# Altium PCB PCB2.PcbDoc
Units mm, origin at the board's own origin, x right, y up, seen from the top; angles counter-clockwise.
Board outline 94.87 x 64.13 mm, 2 copper layers (Top Layer, Bottom Layer); 28 components, 23 nets, 114 pads, 15 vias.
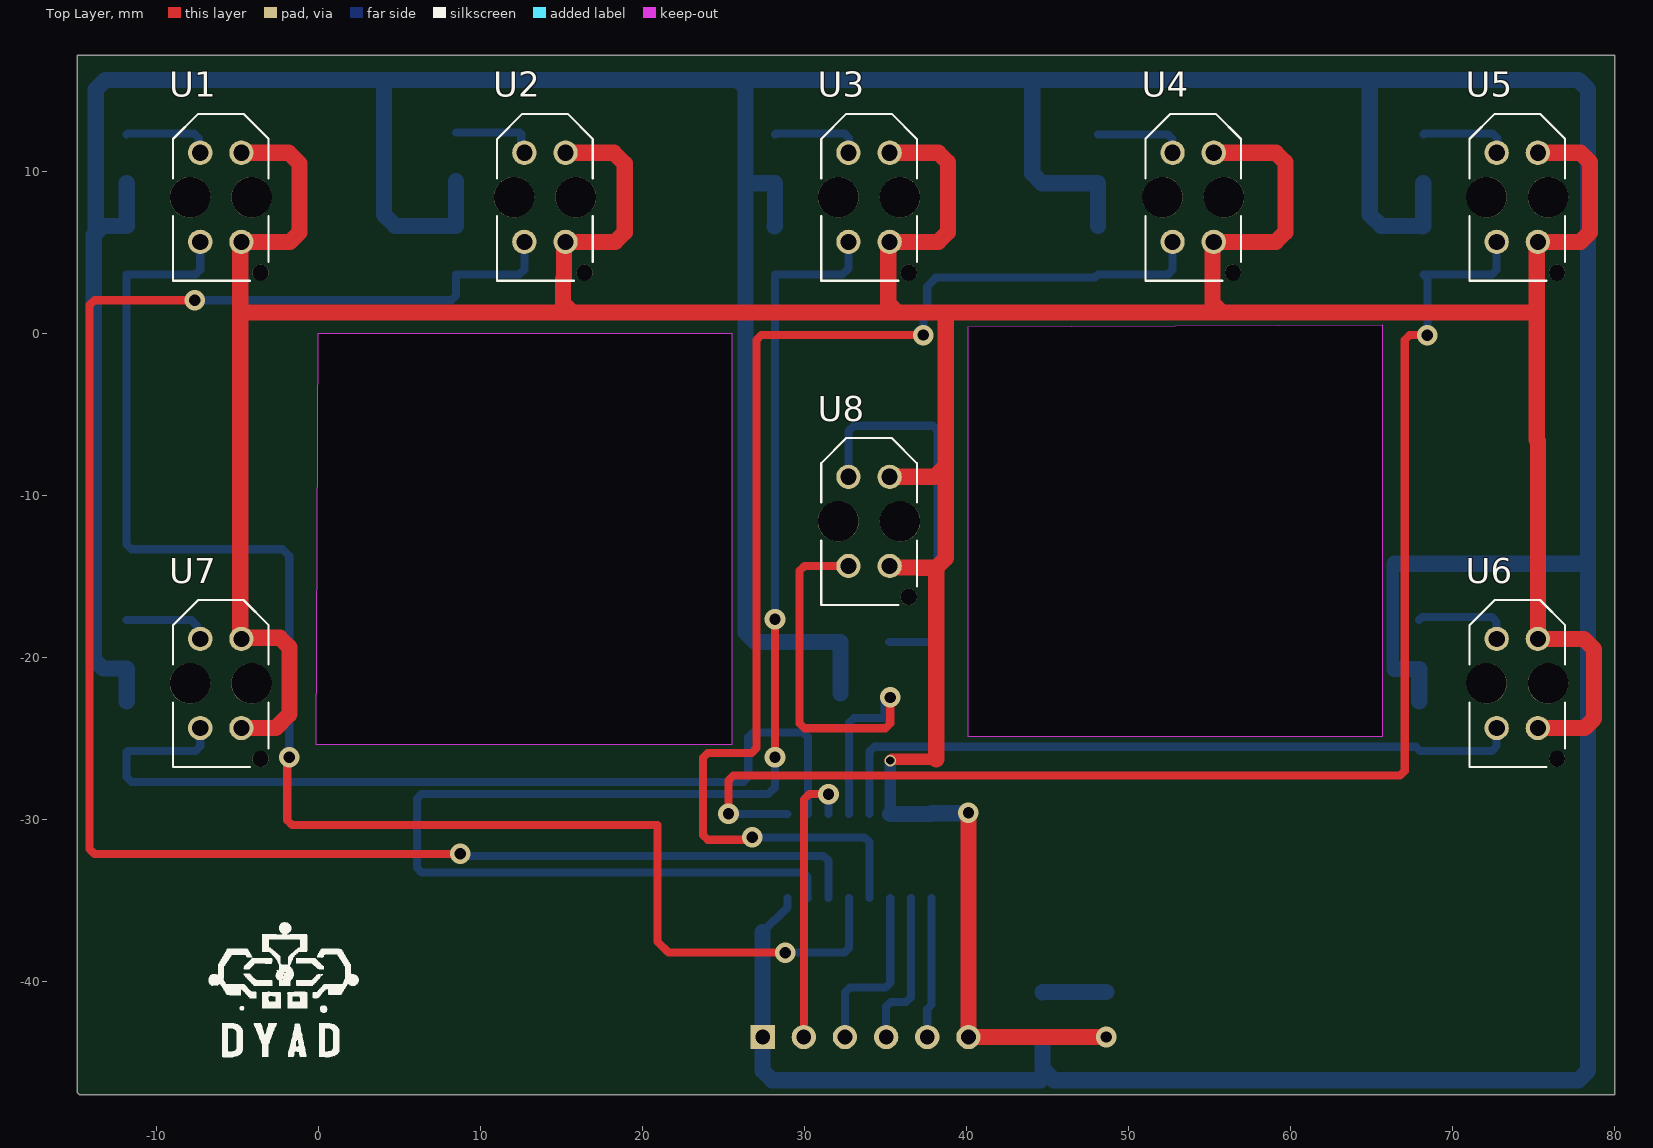
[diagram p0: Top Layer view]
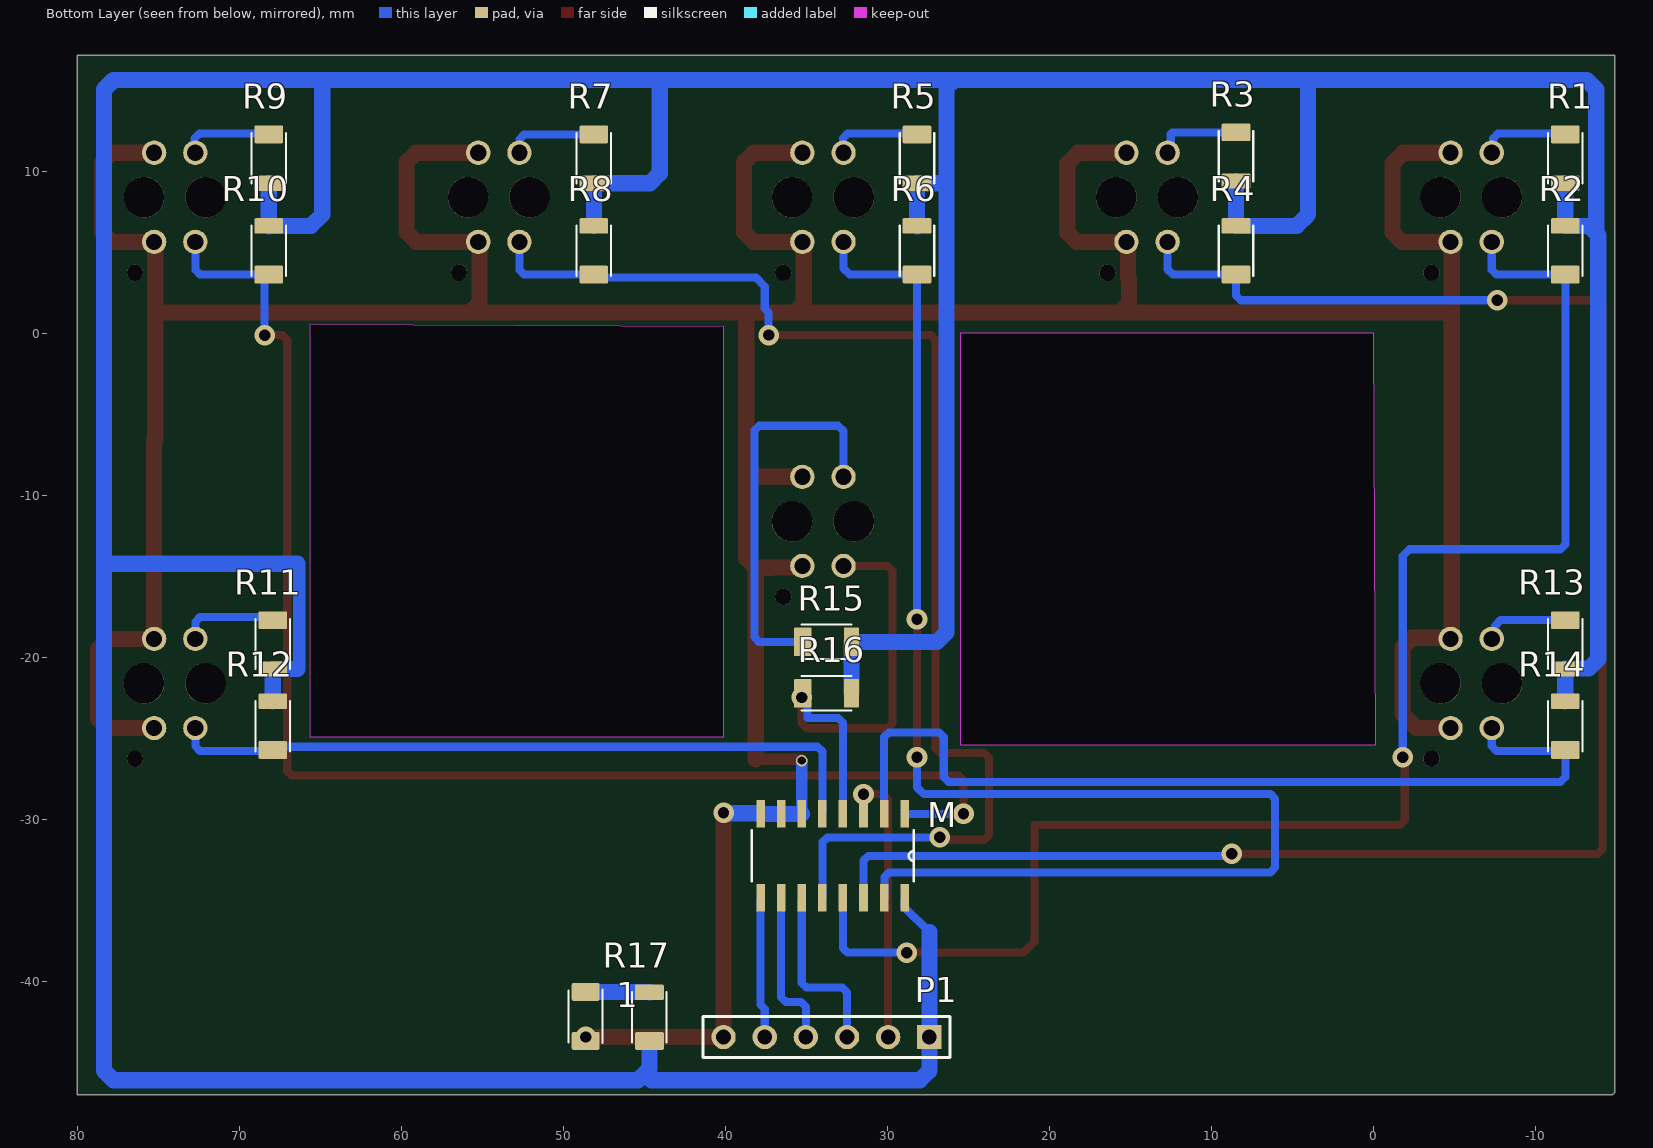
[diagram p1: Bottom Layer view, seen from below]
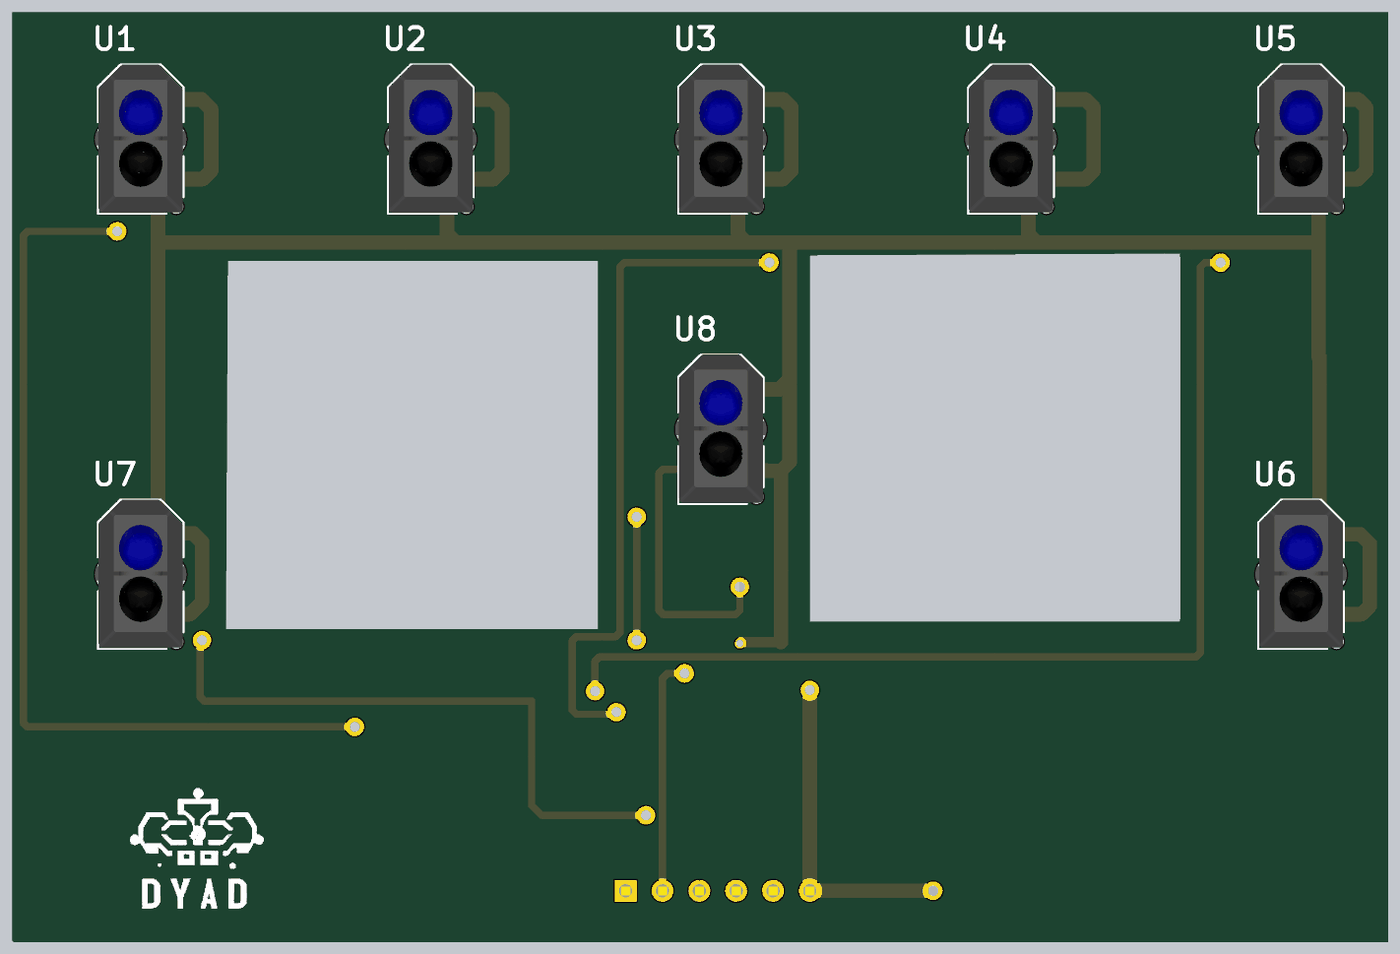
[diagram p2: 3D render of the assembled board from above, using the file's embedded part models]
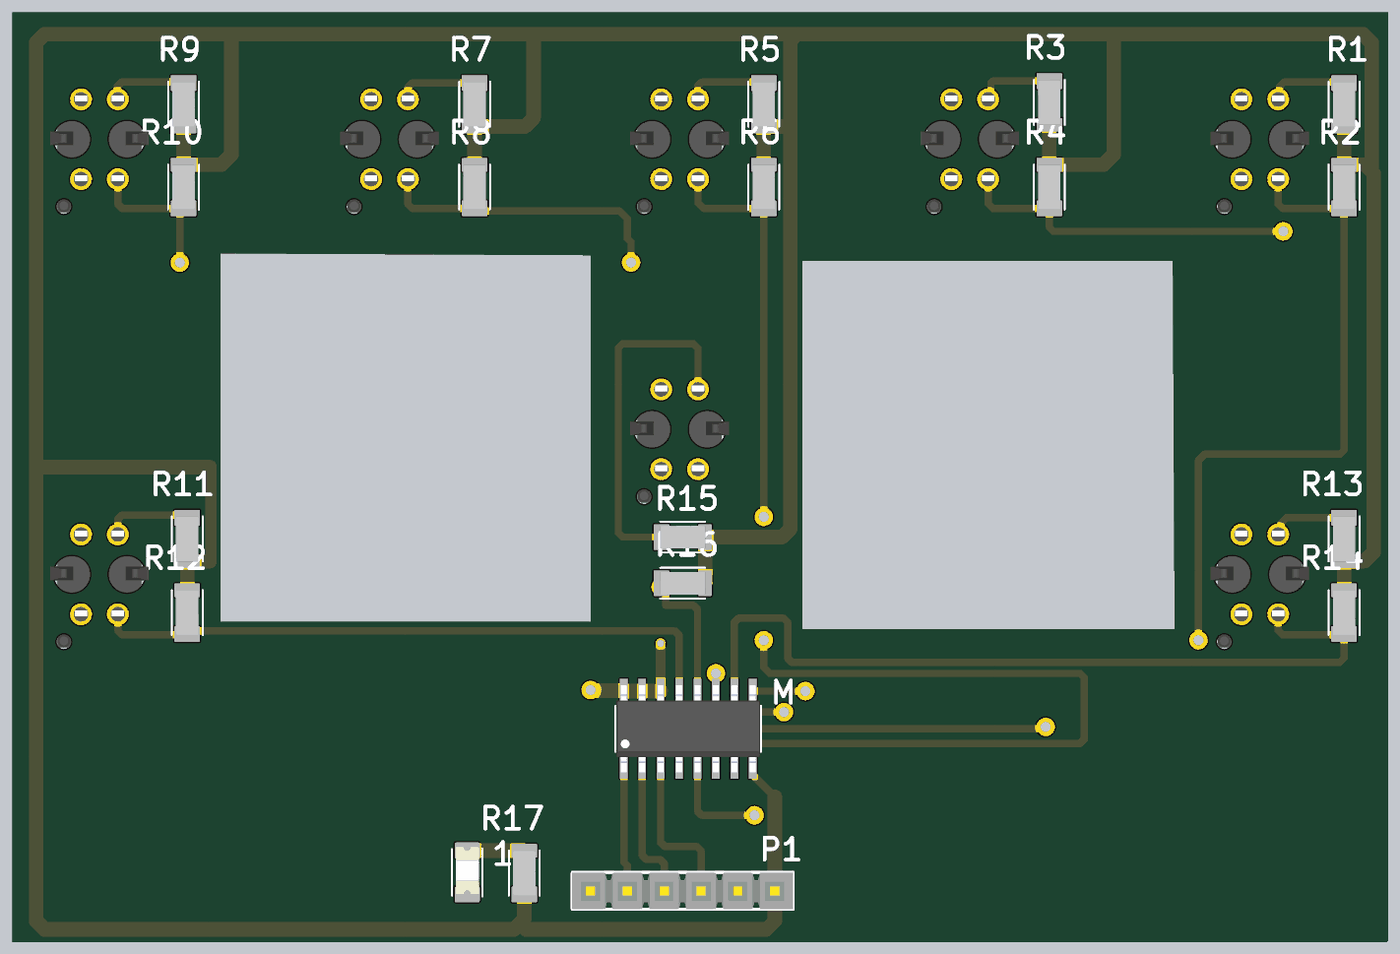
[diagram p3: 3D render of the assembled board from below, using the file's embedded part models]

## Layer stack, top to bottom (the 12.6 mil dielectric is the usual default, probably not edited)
Top Solder: solder mask 0.0102, Solder Resist, Dk 3.5
Top Layer: signal copper 0.0356
Dielectric 1: dielectric 0.32, FR-4, Dk 4.8
Bottom Layer: signal copper 0.0356
Bottom Solder: solder mask 0.0102, Solder Resist, Dk 3.5

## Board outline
-14.732,-46.99 -14.859,-46.863 -14.859,17.145 80.01,17.145 80.01,-46.99
cut-out: 65.659,0.508 65.659,-24.892 40.132,-24.892 40.132,0.381
cut-out: 0,0 25.527,0 25.527,-25.4 -0.127,-25.4

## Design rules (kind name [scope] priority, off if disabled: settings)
Clearance [All] p1: gap=0.254 ignorepadtopadclearanceinfootprint=FALSE except(0: Arc-Hole Track-Hole SMDPad-Hole THPad-Hole Via-Hole Fill-Hole Poly-Hole Region-Hole Text-Hole)
PolygonConnect [All] p1: connectstyle=Relief reliefconductorwidth=0.254 reliefentries=4 polygonreliefangle="90 Angle" airgapwidth=0.254
RoutingVias [All] p1: holewidth=0.711 width=1.27 viastyle="Through Hole" minholewidth=0.711 minwidth=1.27 maxholewidth=0.711 maxwidth=1.27
SolderMaskExpansion [All] p1: expansion=0.102 istentingtop=FALSE
Width [All] p1: maxlimit=2 minlimit=0.5 preferedwidth=1 minimp=50.000000 maximp=50.000000 favimp=50.000000
30 further rules are at their usual default settings.

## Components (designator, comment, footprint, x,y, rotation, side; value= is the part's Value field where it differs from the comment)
1 "LTST-C230KFKT" LEDC3216X110 48.641,-42.164 r90 bottom
M "74HC4051D" SOIC127P600X175-16N 33.401,-32.258 r270 bottom
P1 "Header 6" HDR1X6 27.432,-43.434 r0 bottom
R1 "220" RESC3115X65N -11.811,10.795 r270 bottom
R2 "2K" RESC3115X65N -11.811,5.08 r90 bottom
R3 "220" RESC3115X65N 8.509,10.922 r270 bottom
R4 "2K" RESC3115X65N 8.509,5.08 r90 bottom
R5 "220" RESC3115X65N 28.194,10.795 r270 bottom
R6 "2K" RESC3115X65N 28.194,5.08 r90 bottom
R7 "220" RESC3115X65N 48.133,10.795 r270 bottom
R8 "2K" RESC3115X65N 48.133,5.08 r90 bottom
R9 "220" RESC3115X65N 68.199,10.795 r270 bottom
R10 "2K" RESC3115X65N 68.199,5.08 r90 bottom
R11 "220" RESC3115X65N 67.945,-19.177 r270 bottom
R12 "2K" RESC3115X65N 67.945,-24.257 r90 bottom
R13 "220" RESC3115X65N -11.811,-19.177 r270 bottom
R14 "2K" RESC3115X65N -11.811,-24.257 r90 bottom
R15 "220" RESC3115X65N 33.782,-19.05 r180 bottom
R16 "2K" RESC3115X65N 33.782,-22.225 r180 bottom
R17 "1879462-3" RESC3115X65N 44.704,-42.214 r90 bottom
U1 "IR_SENSOR" OPTO_TCRT5000 -6.002,8.382 r90 top
U2 "IR_SENSOR" OPTO_TCRT5000 13.998,8.382 r90 top
U3 "IR_SENSOR" OPTO_TCRT5000 33.998,8.382 r90 top
U4 "IR_SENSOR" OPTO_TCRT5000 53.998,8.382 r90 top
U5 "IR_SENSOR" OPTO_TCRT5000 73.998,8.382 r90 top
U6 "IR_SENSOR" OPTO_TCRT5000 73.998,-21.618 r90 top
U7 "IR_SENSOR" OPTO_TCRT5000 -6.002,-21.618 r90 top
U8 "IR_SENSOR" OPTO_TCRT5000 33.998,-11.618 r90 top

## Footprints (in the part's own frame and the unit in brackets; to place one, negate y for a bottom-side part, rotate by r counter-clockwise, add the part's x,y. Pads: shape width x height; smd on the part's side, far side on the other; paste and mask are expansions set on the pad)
HDR1X6 [mm] "Connector; Header; 6 Position"
  rect 1.5x1.5 hole 0.9: 1(0,0)
  round 1.5 hole 0.9: 2(2.54,0) 3(5.08,0) 4(7.62,0) 5(10.16,0) 6(12.7,0)
  silkscreen extent -1.27,-1.27 13.97,1.27, body extent -1.26,-1.25 13.98,1.29, height 8.38
LEDC3216X110 [mm]
  rrect20% 1.1x1.73 smd: A(1.51,0) C(-1.51,0)
  silkscreen extent -1.65,-1.04 1.65,1.04, body extent -1.47,-0.8 1.73,0.8, height 1.13
OPTO_TCRT5000 [mm]
  round 1.5 hole 1: A(2.75,1.27) CATH(2.75,-1.27) COLL(-2.75,1.27) E(-2.75,-1.27)
  round 1 hole 1 unplated: ""(-4.65,-2.45)
  round 2.5 hole 2.5 unplated: ""(0,1.9) ""(0,-1.9)
  silkscreen extent -5.15,-2.95 5.15,2.95, body extent -5.04,-3.4 5.16,3.4, height 7.2
RESC3115X65N [mm]
  rrect14% 1.09x1.77 smd: 1(-1.465,0)
  rrect14% 0.94x1.77 smd: 2(1.54,0)
  silkscreen extent -1.55,-1.06 1.55,1.06, body extent -1.55,-0.77 1.55,0.77, height 0.53
SOIC127P600X175-16N [mil]
  rect 67x21 smd: 1(-102,175) 2(-102,125) 3(-102,75) 4(-102,25) 5(-102,-25) 6(-102,-75) 7(-102,-125) 8(-102,-175) 9(102,-175) 10(102,-125) 11(102,-75) 12(102,-25) 13(102,25) 14(102,75) 15(102,125) 16(102,175)
  silkscreen extent -62,-197 62,197, body extent -118,-195 118,195, height 67

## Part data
1: "Orange 605nm LED Indication - Discrete 2V 1206 (3216 Metric)", Package="1206 Lite-On"
M: "1 Circuit IC Switch 8:1 130Ohm 16-SOIC", Package="SOIC-16 Toshiba"
P1: "Header, 6-Pin"
R1 R2 R3 R4 R5 R6 R7 R8 R9 R10 R11 R12 R13 R14 R15 R16: library part 1879462-3, "RL73H 2B R12 1% 5K RL", Package=None
R17: "RL73H 2B R12 1% 5K RL", Package=None
U1 U2 U3 U4 U5 U6 U7 U8: library part TCRT5000, "950 nm 60 mA Through Hole Reflective Optical Sensor with Transistor Output", Package=None

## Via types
v1: diameter 1.27, hole 0.7, Top Layer to Bottom Layer, 14 vias
v2: diameter 0.7, hole 0.5, Top Layer to Bottom Layer, 1 vias

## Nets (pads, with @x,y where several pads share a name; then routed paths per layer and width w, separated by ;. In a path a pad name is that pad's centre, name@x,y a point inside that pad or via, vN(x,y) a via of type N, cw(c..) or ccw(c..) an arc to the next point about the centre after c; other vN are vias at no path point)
+5: M.16 P1.1 R1.2 R2.2 R3.2 R4.2 R5.2 R6.2 R7.2 R8.2 R9.2 R10.2 R11.2 R12.2 R13.2 R14.2 R15.2 R16.2 R17.1 | length 375.8
  Bottom Layer w0.5: 27.432,-36.957 28.956,-35.433 M.16
  Bottom Layer w0.8: 66.413,-20.717 66.406,-20.717 66.313,-20.624 66.313,-14.324 66.413,-14.224
  Bottom Layer w1: R14.2 R13.2 -11.827,-20.701 -13.257,-20.701 -13.843,-20.115 -13.843,6.034 -13.716,6.161 ; R1.2 R2.2 -13.257,6.62 -13.716,6.161 ; R3.2 R4.2 4.761,6.62 4.064,7.317 4.064,15.621 ; 27.432,-36.957 P1.1 27.432,-45.515 28.018,-46.101 44.577,-46.101 44.997,-45.681 ; R6.2@28.164,6.59 R6.2 R5.2 26.367,9.255 ; R16.2 R15.2 26.953,-19.05 26.367,-18.464 26.367,9.255 ; R17.1 44.704,-45.388 45.417,-46.101 77.773,-46.101 78.359,-45.515 78.359,-14.351 ; R8.2 R7.2 44.671,9.255 44.069,9.857 44.069,15.621 ; 66.413,-20.717 R11.2 R12.2 ; 66.413,-14.224 78.232,-14.224 78.359,-14.351 ; R9.2 R10.2 68.169,6.59 68.139,6.62 65.594,6.62 64.897,7.317 64.897,15.621 ; -13.716,6.161 -13.716,15.035 -13.13,15.621 4.064,15.621 ; 4.064,15.621 25.908,15.621 ; 25.908,15.621 44.069,15.621 ; 25.908,15.621 26.367,15.162 26.367,9.255 ; 44.069,15.621 64.897,15.621 ; 64.897,15.621 77.773,15.621 78.359,15.035 78.359,-14.351
A1: M.3 P1.2 | length 17.5
  Top Layer w0.5: P1.2 29.972,-28.783 30.311,-28.444 v1(31.496,-28.444)
  Bottom Layer w0.5: M.3 v1(31.496,-28.444)
D1: M.11 P1.3 | length 11
  Bottom Layer w0.5: P1.3 32.512,-40.679 32.805,-40.386 35.013,-40.386 35.306,-40.093 M.11
D2: M.10 P1.4 | length 9.8
  Bottom Layer w0.5: P1.4 35.052,-41.568 35.345,-41.275 36.283,-41.275 36.576,-40.982 M.10
D3: M.9 P1.5 | length 8.7
  Bottom Layer w0.5: P1.5 37.592,-41.695 37.846,-41.441 M.9
GND: 1.C M.6 M.7 M.8 P1.6 U1.CATH U1.E U2.CATH U2.E U3.CATH U3.E U4.CATH U4.E U5.CATH U5.E U6.CATH U6.E U7.CATH U7.E U8.CATH U8.E | length 294.5
  Top Layer w0.5: U8.E U8.E@35.285,-14.351
  Top Layer w0.7: v2(35.306,-26.377) 35.394,-26.289 38.149,-26.289
  Top Layer w1: U7.E -2.618,-24.368 -1.77,-23.52 -1.77,-19.382 -2.356,-18.796 -4.66,-18.796 U7.CATH -4.806,-18.794 -4.806,1.27 ; U1.CATH -1.812,11.132 -1.143,10.463 -1.143,6.218 -1.729,5.632 U1.E -4.806,5.558 -4.806,1.27 ; U2.CATH 18.254,11.132 18.923,10.463 18.923,6.218 18.337,5.632 U2.E 15.172,5.536 15.172,3.401 15.113,3.342 15.113,1.856 15.699,1.27 ; U8.E 35.364,-14.464 37.135,-14.464 37.149,-14.478 38.149,-14.478 ; U8.CATH 38.044,-8.868 38.735,-8.177 ; U3.CATH 38.276,11.132 38.862,10.546 38.862,6.218 38.276,5.632 U3.E 35.179,5.543 35.179,1.856 35.765,1.27 ; 38.149,-26.289 38.149,-14.478 ; v1(40.132,-29.591) P1.6 v1(48.641,-43.434) ; U4.CATH 59.104,11.132 59.69,10.546 59.69,6.218 59.104,5.632 U4.E 55.194,5.558 55.194,1.856 55.78,1.27 ; U6.E 78.154,-24.368 78.74,-23.782 78.74,-19.509 78.099,-18.868 U6.CATH 75.268,-6.655 75.194,-6.581 75.194,1.27 ; U5.CATH 77.9,11.132 78.486,10.546 78.486,6.218 77.9,5.632 U5.E 75.194,5.558 75.194,1.27 ; -4.806,1.27 15.699,1.27 ; 15.699,1.27 35.765,1.27 ; 35.765,1.27 38.735,1.27 ; 38.149,-14.478 38.735,-13.892 38.735,-8.177 ; 38.735,-8.177 38.735,1.27 ; 38.735,1.27 55.78,1.27 ; 55.78,1.27 75.194,1.27
  Bottom Layer w0.7: M.6 v2(35.306,-26.377)
  Bottom Layer w1: U1.E@-4.806,5.558 U1.E ; U2.CATH U2.CATH@15.364,11.228 ; M.6 M.7 M.8 37.884,-29.629 40.094,-29.629 v1(40.132,-29.591)
Net1_A: 1.A R17.2 | length 3.9
  Bottom Layer w1: R17.2 44.714,-40.664 48.631,-40.664 1.A
NetR1_1: R1.1 U1.A | length 5.5
  Bottom Layer w0.5: R1.1 -11.752,12.319 -7.659,12.319 -7.366,12.026 -7.366,11.226 U1.A
NetR3_1: R3.1 U2.A | length 5.3
  Bottom Layer w0.5: R3.1 12.435,12.387 12.537,12.285 12.537,11.323 U2.A
NetR5_1: R5.1 U3.A | length 5.6
  Bottom Layer w0.5: R5.1 28.253,12.319 32.473,12.319 32.766,12.026 32.766,11.17 U3.A
NetR7_1: R7.1 U4.A | length 5.6
  Bottom Layer w0.5: R7.1 52.435,12.26 52.728,11.967 U4.A
NetR9_1: R9.1 U5.A | length 5.6
  Bottom Layer w0.5: R9.1 68.258,12.319 72.478,12.319 72.771,12.026 72.771,11.175 U5.A
NetR11_1: R11.1 U6.A | length 6.1
  Top Layer w0.5: U6.A@72.644,-18.784 U6.A
  Bottom Layer w0.5: R11.1 68.131,-17.526 72.435,-17.526 72.728,-17.819 U6.A
NetR13_1: R13.1 U7.A | length 5.4
  Bottom Layer w0.5: R13.1 -7.823,-17.712 -7.463,-18.072 -7.463,-18.677 U7.A
NetR15_1: R15.1 U8.A | length 24.7
  Bottom Layer w0.5: U8.A@32.919,-9.059 U8.A 32.728,-6.046 33.059,-5.715 37.934,-5.715 38.227,-6.008 38.227,-18.757 37.934,-19.05 R15.1
S1: M.13 R2.1 U1.COLL | length 95.2
  Top Layer w0.5: v1(-1.778,-26.162) -1.905,-26.289 -1.905,-30.06 -1.612,-30.353 20.955,-30.353 20.955,-37.553 21.629,-38.227 v1(28.833,-38.227)
  Bottom Layer w0.5: U1.COLL -7.272,3.908 -7.565,3.615 R2.1 -11.811,-13.042 -11.518,-13.335 -2.198,-13.335 -1.778,-13.755 v1(-1.778,-26.162) ; v1(28.833,-38.227) 32.473,-38.227 32.766,-37.934 M.13
S2: M.14 R4.1 U2.COLL | length 112
  Top Layer w0.5: v1(-7.62,2.032) -13.804,2.032 -14.097,1.739 -14.097,-31.842 -13.804,-32.135 v1(8.763,-32.135)
  Bottom Layer w0.5: v1(-7.62,2.032) 8.216,2.032 8.509,2.325 R4.1 12.407,3.615 12.728,3.936 U2.COLL ; v1(8.763,-32.135) 8.886,-32.258 31.203,-32.258 31.496,-32.551 M.14
S3: M.15 R6.1 U3.COLL | length 90.3
  Top Layer w0.5: v1(28.194,-26.166) v1(28.194,-17.653)
  Bottom Layer w0.5: v1(28.194,-26.166) 28.194,-28.028 27.774,-28.448 6.389,-28.448 6.096,-28.741 6.096,-32.981 6.389,-33.274 29.933,-33.274 30.209,-33.55 30.209,-34.832 M.15 ; v1(28.194,-17.653) R6.1 32.346,3.615 32.728,3.997 U3.COLL
S4: M.12 R8.1 U4.COLL | length 78.3
  Top Layer w0.5: v1(26.797,-31.115) 26.65,-31.262 24.042,-31.262 23.749,-30.969 23.749,-26.201 24.042,-25.908 26.758,-25.908 27.055,-25.611 27.055,-0.412 27.348,-0.119 v1(37.346,-0.119)
  Bottom Layer w0.5: v1(26.797,-31.115) 33.726,-31.115 34.019,-31.408 34.019,-34.832 M.12 ; v1(37.346,-0.119) 37.346,1.27 37.592,1.516 37.592,2.882 38.139,3.429 47.947,3.429 R8.1 52.435,3.615 52.728,3.908 U4.COLL
S5: M.1 R10.1 U5.COLL | length 86
  Top Layer w0.5: v1(25.324,-29.667) 25.324,-27.598 25.617,-27.305 66.763,-27.305 67.056,-27.012 67.056,-0.42 67.349,-0.127 v1(68.453,-0.127)
  Bottom Layer w0.5: v1(25.324,-29.667) M.1 ; v1(68.453,-0.127) 68.453,3.361 R10.1 72.435,3.615 72.728,3.908 U5.COLL
S6: M.5 R12.1 U6.COLL | length 44.3
  Top Layer w0.5: U6.COLL@72.537,-24.559 U6.COLL
  Bottom Layer w0.5: M.5 34.036,-25.816 34.329,-25.523 67.746,-25.523 68.004,-25.781 72.435,-25.781 72.728,-25.488 U6.COLL
S7: M.2 R14.1 U7.COLL | length 57.1
  Bottom Layer w0.5: U7.COLL -7.272,-25.488 -7.565,-25.781 -11.752,-25.781 -11.811,-25.84 -11.811,-27.393 -11.518,-27.686 26.25,-27.686 26.543,-27.393 26.543,-24.931 26.836,-24.638 29.933,-24.638 30.226,-24.931 M.2
S8: M.4 R16.1 U8.COLL | length 29.6
  Top Layer w0.5: U8.COLL 30.011,-14.368 29.718,-14.661 29.718,-24.091 30.011,-24.384 35.013,-24.384 35.306,-24.091 v1(35.306,-22.479)
  Bottom Layer w0.5: M.4 32.766,-24.042 33.059,-23.749 34.954,-23.749 34.954,-22.518 R16.1
pads on no net: U1. U2. U3. U4. U5. U6. U7. U8.

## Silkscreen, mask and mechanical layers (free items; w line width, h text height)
Top Overlay:
  drawing of 17 lines, arcs and shapes, not listed
Mechanical 1:
  lines w0.254: -14.859,-46.863 -14.732,-46.99 80.01,-46.99 80.01,-45.212 80.01,17.145 -14.859,17.145 -14.859,-46.863 ; 0,-25.4 0,0 25.527,0 25.527,-25.273 25.4,-25.4 0,-25.4 ; 40.132,-24.892 65.532,-24.892 65.659,-24.765 65.659,0.508 40.132,0.508 40.132,-24.892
